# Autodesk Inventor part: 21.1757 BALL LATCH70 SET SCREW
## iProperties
Created: 2007-03
Part Number: 21.1757 BALL LATCH70 SET SCREW
Document SubType Name: Modeling
Designer: Andy Moles
Material: Steel
Density: 7.85 g/cm^3
Author: Andy Moles
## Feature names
1. Extrusion1
2. Extrusion2
